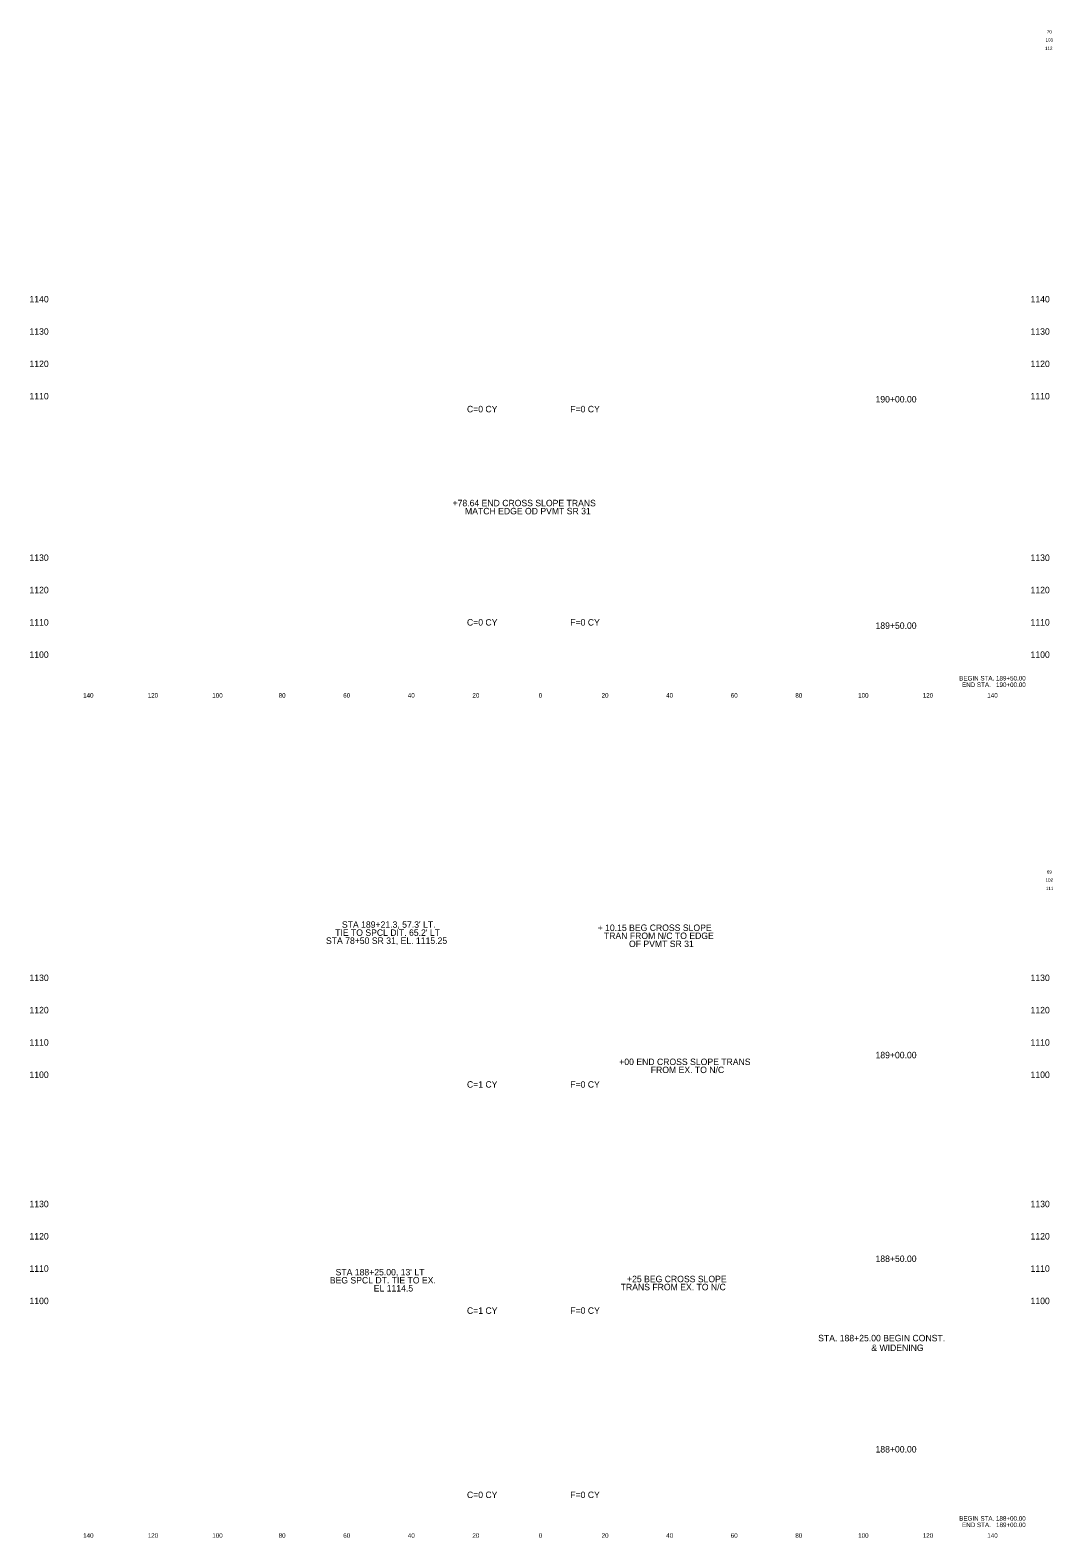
# Model space of a CAD drawing. Extents: x 1002 to 1319, y 998 to 1464.
import ezdxf

# ---------------------------------------------------------------- set-up
doc = ezdxf.new("R2010")
doc.units = 0
for name, color, linetype in [('Default', 7, 'Continuous'), ('DESIGN - DRAINAGE - Text', 7, 'Continuous'), ('DESIGN - SHEET - Corner Text', 7, 'Continuous'), ('DESIGN - TYPICAL - Finished Grade Slopes Text', 7, 'Continuous'), ('DESIGN - TYPICAL - Text', 7, 'Continuous')]:
    doc.layers.add(name, color=color, linetype=linetype)

msp = doc.modelspace()

# ---------------------------------------------------------------- texts
at = {"layer": 'Default'}
for s, height, p in [('     1140     ', 2, (998.01, 1380)), ('     1140     ', 2, (1308.01, 1380)), ('     1130     ', 2, (998.01, 1370)), ('     1130     ', 2, (1308.01, 1370)), ('     1120     ', 2, (998.01, 1360)), ('     1120     ', 2, (1308.01, 1360)), ('     1110     ', 2, (998.01, 1350)), ('     190+00.00     ', 2, (1260, 1349.04)), ('     1110     ', 2, (1308.01, 1350)), ('     1130     ', 2, (998.01, 1300)), ('     1130     ', 2, (1308.01, 1300)), ('     1120     ', 2, (998.01, 1290)), ('     1120     ', 2, (1308.01, 1290)), ('     1110     ', 2, (998.01, 1280)), ('     189+50.00     ', 2, (1260, 1278.98)), ('     1110     ', 2, (1308.01, 1280)), ('     1100     ', 2, (998.01, 1270)), ('     1100     ', 2, (1308.01, 1270)), ('     140     ', 1.4, (1015.65, 1257.7)), ('     120     ', 1.4, (1035.65, 1257.7)), ('     100     ', 1.4, (1055.65, 1257.7)), ('     80     ', 1.4, (1076.2, 1257.7)), ('     60     ', 1.4, (1096.2, 1257.7)), ('     40     ', 1.4, (1116.2, 1257.7)), ('     20     ', 1.4, (1136.2, 1257.7)), ('     0     ', 1.4, (1156.74, 1257.7)), ('     0     ', 1.4, (1156.74, 1257.7)), ('     20     ', 1.4, (1176.2, 1257.7)), ('     40     ', 1.4, (1196.2, 1257.7)), ('     60     ', 1.4, (1216.2, 1257.7)), ('     80     ', 1.4, (1236.2, 1257.7)), ('     100     ', 1.4, (1255.65, 1257.7)), ('     120     ', 1.4, (1275.65, 1257.7)), ('     140     ', 1.4, (1295.65, 1257.7)), ('     1130     ', 2, (998.01, 1170)), ('     1130     ', 2, (1308.01, 1170)), ('     1120     ', 2, (998.01, 1160)), ('     1120     ', 2, (1308.01, 1160)), ('     1110     ', 2, (998.01, 1150)), ('     189+00.00     ', 2, (1260, 1146.09)), ('     1110     ', 2, (1308.01, 1150)), ('     1100     ', 2, (998.01, 1140)), ('     1100     ', 2, (1308.01, 1140)), ('     1130     ', 2, (998.01, 1100)), ('     1130     ', 2, (1308.01, 1100)), ('     1120     ', 2, (998.01, 1090)), ('     1120     ', 2, (1308.01, 1090)), ('     188+50.00     ', 2, (1260, 1083.05)), ('     1110     ', 2, (998.01, 1080)), ('     1110     ', 2, (1308.01, 1080)), ('     1100     ', 2, (998.01, 1070)), ('     1100     ', 2, (1308.01, 1070)), ('     188+00.00     ', 2, (1260, 1024.09)), ('     140     ', 1.4, (1015.65, 997.7)), ('     120     ', 1.4, (1035.65, 997.7)), ('     100     ', 1.4, (1055.65, 997.7)), ('     80     ', 1.4, (1076.2, 997.7)), ('     60     ', 1.4, (1096.2, 997.7)), ('     40     ', 1.4, (1116.2, 997.7)), ('     20     ', 1.4, (1136.2, 997.7)), ('     0     ', 1.4, (1156.74, 997.7)), ('     0     ', 1.4, (1156.74, 997.7)), ('     20     ', 1.4, (1176.2, 997.7)), ('     40     ', 1.4, (1196.2, 997.7)), ('     60     ', 1.4, (1216.2, 997.7)), ('     80     ', 1.4, (1236.2, 997.7)), ('     100     ', 1.4, (1255.65, 997.7)), ('     120     ', 1.4, (1275.65, 997.7)), ('     140     ', 1.4, (1295.65, 997.7))]:
    msp.add_text(s, height=height, dxfattribs=at).set_placement(p)
at = {"layer": 'DESIGN - DRAINAGE - Text'}
for s, p in [("TIE TO SPCL DIT. 65.2' LT", (1096.38, 1183.98)), ("STA 189+21.3, 57.3' LT.", (1098.48, 1186.47)), ('STA 78+50 SR 31, EL. 1115.25', (1093.54, 1181.49)), ('BEG SPCL DT. TIE TO EX.', (1094.73, 1076.4)), ("STA 188+25.00, 13' LT", (1096.53, 1078.89)), ('EL 1114.5', (1108.33, 1073.91))]:
    msp.add_text(s, height=2, dxfattribs=at).set_placement(p)
at = {"layer": 'DESIGN - SHEET - Corner Text'}
for s, height, p in [('103', 1, (1316.37, 1460.75)), ('70', 1, (1316.76, 1463.25)), ('112', 1, (1316.21, 1458.15)), ('BEGIN STA. 189+50.00', 1.4, (1289.64, 1263)), ('END STA.   190+00.00', 1.4, (1290.51, 1261)), ('69', 1, (1316.75, 1203.25)), ('102', 1, (1316.37, 1200.75)), ('111', 1, (1316.47, 1198.15)), ('BEGIN STA. 188+00.00', 1.4, (1289.64, 1003)), ('END STA.   189+00.00', 1.4, (1290.51, 1001))]:
    msp.add_text(s, height=height, dxfattribs=at).set_placement(p)
at = {"layer": 'DESIGN - TYPICAL - Finished Grade Slopes Text'}
for s, p in [('+78.64 END CROSS SLOPE TRANS', (1132.74, 1316.92)), ('MATCH EDGE OD PVMT SR 31', (1136.6, 1314.43)), ('+ 10.15 BEG CROSS SLOPE ', (1177.67, 1185.49)), ('TRAN FROM N/C TO EDGE', (1179.62, 1183)), ('OF PVMT SR 31', (1187.38, 1180.51)), ('+00 END CROSS SLOPE TRANS', (1184.37, 1144)), ('FROM EX. TO N/C', (1194.12, 1141.51)), ('+25 BEG CROSS SLOPE', (1186.77, 1076.79)), ('TRANS FROM EX. TO N/C', (1184.81, 1074.3))]:
    msp.add_text(s, height=2, dxfattribs=at).set_placement(p)
at = {"layer": 'DESIGN - TYPICAL - Text'}
for s, p in [('C=0 CY', (1137.2, 1346)), ('F=0 CY', (1169.2, 1346)), ('C=0 CY', (1137.2, 1280)), ('F=0 CY', (1169.2, 1280)), ('C=1 CY', (1137.2, 1137)), ('F=0 CY', (1169.2, 1137)), ('C=1 CY', (1137.2, 1067)), ('F=0 CY', (1169.2, 1067)), ('STA. 188+25.00 BEGIN CONST. ', (1245.95, 1058.5)), ('& WIDENING', (1262.42, 1055.5)), ('C=0 CY', (1137.2, 1010)), ('F=0 CY', (1169.2, 1010))]:
    msp.add_text(s, height=2, dxfattribs=at).set_placement(p)

doc.saveas('drawing.dxf')
